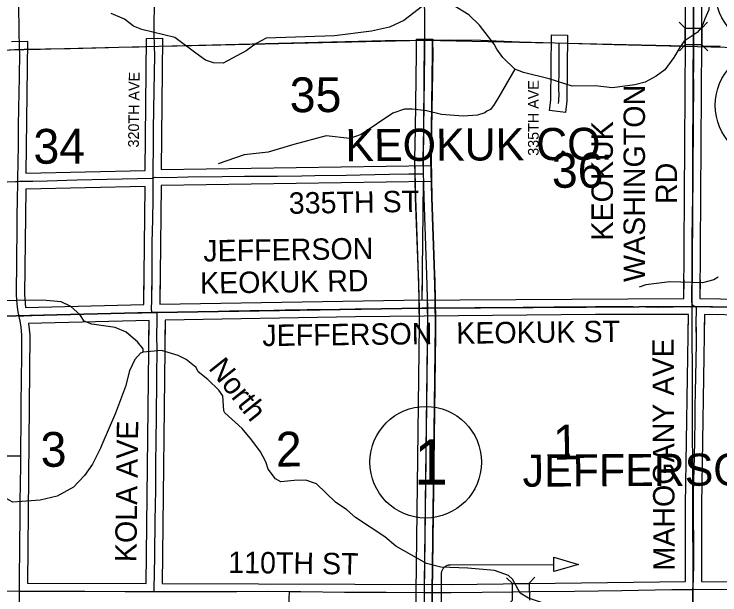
# Model space of a CAD drawing. Extents: x 10133 to 81668, y 7924 to 11018.
# Drawn here: x 11826.5 to 12222.4, y 8891.7 to 9217.2 of the extents above; entities that cross this region are included whole.
import ezdxf

# ---------------------------------------------------------------- set-up
doc = ezdxf.new("R2010")
doc.units = 0
for name, color, linetype in [('tdCoCityStreetMajor', 7, 'Continuous'), ('tdCoCityStreetMinor', 7, 'Continuous'), ('tdCoCorpPopTxt', 7, 'Continuous'), ('tdCoCorpTxt', 7, 'Continuous'), ('tdCoDirctArrow', 7, 'Continuous'), ('tdCoHydroRiver', 7, 'Continuous'), ('tdCoPriNonDiv', 7, 'Continuous'), ('tdCoRROwnerTxt', 7, 'Continuous'), ('tdCoSecRdTxt', 7, 'Continuous'), ('tdCoSectLinePart', 7, 'Continuous'), ('tdCoShieldCoRte', 7, 'Continuous'), ('tdCoShieldCoRteHrd', 7, 'Continuous'), ('tdCoShieldStRte', 7, 'Continuous'), ('tdCoStrucNonDivPri', 7, 'Continuous'), ('tdCoStrucSec', 7, 'Continuous'), ('tdCoSurfAsphalt', 7, 'Continuous'), ('tdCoSurfConc', 7, 'Continuous'), ('tdCoSurfGravel', 7, 'Continuous'), ('tdCoTwpBndryShd', 7, 'Continuous'), ('tdCoTwpNameTxt', 7, 'Continuous')]:
    doc.layers.add(name, color=color, linetype=linetype)

msp = doc.modelspace()

# ---------------------------------------------------------------- linework, layer by layer
at = {"layer": 'tdCoCityStreetMajor'}
for points in [[(11828.65, 9123.44), (11829.54, 9123.5), (11836.99, 9123.57), (11845.15, 9123.82), (11861.68, 9124.31), (11878.69, 9124.68), (11904.19, 9125.22), (11904.5, 9125.34), (11905.55, 9125.72), (11912.23, 9125.67), (11923.92, 9125.96), (11943.18, 9126.11), (11955.71, 9126.28), (11974.25, 9126.43), (11987.97, 9126.58)], [(11906.48, 8998.16), (11906.56, 9005.55), (11906.6, 9014.76), (11906.67, 9028.63), (11906.6, 9037.44), (11906.67, 9044.74), (11906.69, 9050.03)], [(11906.62, 9035.02), (11906.6, 9037.44), (11906.67, 9044.74), (11906.69, 9050.03)], [(12132.92, 9053.1), (12146.45, 9053.08), (12152.66, 9053.23), (12166.25, 9053.23), (12173.75, 9053.23), (12187.73, 9052.98), (12196.26, 9053.15), (12206.35, 9053.3), (12208.48, 9053.22)], [(12132.92, 9053.1), (12146.45, 9053.08), (12152.66, 9053.22), (12166.25, 9053.22), (12173.75, 9053.22), (12187.73, 9052.98), (12196.26, 9053.15), (12206.35, 9053.3), (12208.48, 9053.22)], [(11980.11, 8818.02), (11980.38, 8846.28), (11980.64, 8866.11), (11980.71, 8874.88), (11980.86, 8889.49), (11980.98, 8893.53)]]:
    msp.add_lwpolyline(points, dxfattribs=at)
at = {"layer": 'tdCoCityStreetMinor'}
for points in [[(12208.48, 9053.22), (12207.55, 9053.71), (12207.23, 9054.06), (12206.89, 9054.7), (12206.71, 9055.66), (12206.74, 9060.42), (12206.79, 9069.84), (12206.89, 9080.84), (12206.91, 9092.04), (12207.03, 9103.58), (12207.13, 9115.44), (12207.21, 9125.43), (12207.21, 9129.47), (12207.26, 9140.64), (12207.3, 9151.77), (12207.4, 9159.04), (12207.43, 9163.92), (12207.5, 9174.55), (12207.45, 9185.92), (12207.63, 9198), (12207.64, 9199.23), (12207.67, 9201.63), (12207.58, 9216.6), (12207.5, 9229.13)], [(12131.89, 9167.05), (12132.11, 9168.68), (12132.18, 9172.55), (12132.13, 9174.57), (12132.11, 9178.84), (12132.21, 9183.35), (12132.23, 9189.74), (12132.31, 9195.12), (12132.26, 9199.75), (12132.28, 9201.05)], [(11828.65, 9123.44), (11828.64, 9124.96), (11828.76, 9134.03), (11828.89, 9143.77), (11829.06, 9154.38), (11829.26, 9164.5), (11829.51, 9181.76), (11829.66, 9195.82), (11829.62, 9197.4)], [(11903.94, 9049.97), (11903.64, 9051.32), (11903.74, 9057.39), (11903.89, 9067.52), (11903.98, 9078.33), (11904.03, 9088.56), (11904.18, 9096.33), (11904.26, 9101.31), (11904.43, 9114.21), (11904.5, 9124.05), (11904.5, 9125.34), (11904.5, 9127.45), (11904.55, 9132.41), (11904.65, 9140.35), (11904.7, 9144.27), (11904.78, 9152.86), (11905.07, 9174.22), (11905.37, 9194.09), (11905.29, 9199.19)], [(11987.97, 9126.58), (11995.12, 9126.65), (12012.75, 9126.95), (12020.63, 9127.16), (12037.01, 9127.46), (12047.96, 9127.66), (12056, 9127.73)], [(11790.62, 9122.52), (11796.94, 9122.68), (11800.2, 9122.78), (11811.71, 9123.03), (11822.69, 9123.25), (11827.28, 9123.35), (11828.65, 9123.44)], [(11829.36, 9047.87), (11828.86, 9050.31), (11828.39, 9052.9), (11828.05, 9057.02), (11827.78, 9059.78), (11827.8, 9065.01), (11827.97, 9074.25), (11828.05, 9083.8), (11828.17, 9092.97), (11828.27, 9103.72), (11828.49, 9113.64), (11828.66, 9122.27), (11828.65, 9123.44)], [(12208.48, 9053.22), (12207.55, 9053.72), (12207.23, 9054.06), (12206.89, 9054.7), (12206.71, 9055.66), (12206.74, 9060.42), (12206.78, 9068.28)], [(11829.36, 9047.87), (11828.86, 9050.31), (11828.39, 9052.9), (11828.05, 9057.02), (11827.78, 9059.78), (11827.79, 9062.93)], [(11903.94, 9049.97), (11903.64, 9051.32), (11903.74, 9057.39), (11903.85, 9064.96)], [(11829.36, 9047.87), (11830.33, 9048.12), (11831.88, 9048.14), (11841.5, 9048.39), (11843.44, 9048.42), (11860.16, 9049.01), (11864.68, 9049.06), (11877.92, 9049.35), (11888.28, 9049.53), (11898.14, 9049.84), (11903.94, 9049.97)], [(11829.36, 9047.87), (11830.33, 9048.12), (11831.88, 9048.14), (11841.5, 9048.39), (11843.44, 9048.41), (11860.16, 9049.01), (11864.68, 9049.06), (11877.92, 9049.35), (11888.28, 9049.52), (11898.14, 9049.84), (11903.94, 9049.97)], [(11903.94, 9049.97), (11906.69, 9050.03), (11914.93, 9050.21), (11930.89, 9050.56), (11940.85, 9050.76), (11947.27, 9050.83), (11958.68, 9051.01), (11972.2, 9051.25), (11978.54, 9051.35), (11990.87, 9051.57), (12000.56, 9051.65), (12008.99, 9051.85), (12017.87, 9052), (12024.87, 9052.05), (12035.33, 9052.2), (12045.24, 9052.35), (12058.43, 9052.45), (12066.28, 9052.53), (12071.88, 9052.53), (12084.95, 9052.66), (12091.65, 9052.76), (12103.84, 9052.81), (12112.1, 9052.88), (12129.21, 9053.1), (12132.92, 9053.1)], [(11903.94, 9049.97), (11906.69, 9050.03), (11914.93, 9050.21), (11930.89, 9050.56), (11940.85, 9050.76), (11947.27, 9050.83), (11958.68, 9051), (11972.2, 9051.25), (11978.54, 9051.35), (11990.87, 9051.57), (12000.56, 9051.65), (12008.99, 9051.85), (12017.87, 9052), (12024.87, 9052.05), (12035.33, 9052.2), (12045.24, 9052.34), (12058.43, 9052.45), (12066.28, 9052.53), (12071.88, 9052.53), (12084.95, 9052.66), (12091.65, 9052.76), (12103.84, 9052.8), (12112.1, 9052.88), (12129.21, 9053.1), (12132.92, 9053.1)], [(12207.13, 8882.11), (12207.13, 8893.09), (12207.28, 8894.75), (12207.46, 8896.75), (12207.65, 8900.34), (12207.68, 8902.89), (12207.79, 8907.15), (12207.79, 8923.02), (12207.57, 8933.23), (12207.57, 8942.29), (12207.65, 8948.58), (12207.79, 8955.9), (12208.13, 8969.03), (12208.31, 8978.02), (12208.53, 8989.64), (12208.61, 8997.7), (12208.68, 9005.06), (12209.05, 9023.19), (12209.24, 9032.84), (12209.15, 9044.91), (12209.16, 9045.16), (12209.28, 9050.56), (12209.3, 9052.43), (12209.3, 9053.23)], [(12208.48, 9053.22), (12208.64, 9053.2), (12209.3, 9053.23)], [(12208.48, 9053.22), (12208.48, 9053.22)], [(12208.48, 9053.22), (12208.64, 9053.2), (12209.3, 9053.22)], [(12208.48, 9053.22), (12208.48, 9053.22)], [(12209.2, 9038.83), (12209.15, 9044.91), (12209.16, 9045.16), (12209.28, 9050.56), (12209.3, 9052.43), (12209.3, 9053.22)], [(12209.3, 9053.23), (12210.41, 9053.27), (12217.22, 9053.2), (12217.61, 9053.2), (12238.26, 9052.74), (12245.77, 9052.78), (12259.53, 9052.56), (12273.74, 9052.22), (12286.16, 9052.11), (12298.89, 9051.89), (12307.84, 9051.74), (12315.91, 9051.59), (12325.97, 9051.41), (12337.95, 9051.19), (12350.97, 9051), (12354.1, 9050.96)], [(12209.3, 9053.22), (12210.41, 9053.27), (12217.22, 9053.2), (12217.61, 9053.2), (12221.65, 9053.11)], [(11830.35, 8969.55), (11830.35, 8971.24), (11830.46, 8990.26), (11830.53, 8997.29), (11830.64, 9013.71), (11830.79, 9024.62), (11830.86, 9037.41), (11830.41, 9041.8), (11829.9, 9045.23), (11829.63, 9046.59), (11829.36, 9047.87)], [(11830.84, 9033.02), (11830.86, 9037.41), (11830.41, 9041.8), (11829.9, 9045.23), (11829.63, 9046.58), (11829.36, 9047.87)], [(11905.06, 8893.57), (11905.08, 8895.13), (11905.38, 8913.22), (11905.64, 8934.19), (11905.75, 8940.85), (11905.93, 8951.61), (11906.08, 8962.93), (11906.27, 8980.36), (11906.38, 8988.75), (11906.48, 8998.16)], [(11770.39, 8969.32), (11788, 8969.34), (11809.75, 8969.68), (11813.71, 8969.68), (11830.35, 8969.55)], [(11829.54, 8893.79), (11829.57, 8898.89), (11829.76, 8919.83), (11829.9, 8934.99), (11829.98, 8943.72), (11830.35, 8963.99), (11830.35, 8969.55)], [(11677.96, 8893.57), (11686.46, 8893.65), (11715.42, 8893.76), (11735.36, 8893.83), (11751.89, 8893.83), (11767.47, 8893.83), (11788.41, 8893.95), (11813.85, 8893.83), (11829.54, 8893.79)], [(11829.5, 8887.46), (11829.54, 8893.79)], [(11829.54, 8893.79), (11836.17, 8893.76), (11866.2, 8893.69), (11888.77, 8893.62), (11905.06, 8893.57)], [(11905.06, 8893.57), (11912.78, 8893.54), (11951.43, 8893.58), (11968.56, 8893.65), (11980.98, 8893.53), (11987.42, 8893.47), (12011.84, 8893.25), (12035.18, 8893.17), (12056.5, 8893.05)]]:
    msp.add_lwpolyline(points, dxfattribs=at)
at = {"layer": 'tdCoCorpPopTxt'}
msp.add_lwpolyline([(11905.29, 9199.19), (11905.17, 9206.37), (11905.22, 9227.48), (11905.09, 9246.02), (11905.02, 9248.69), (11905.01, 9248.71), (11904.97, 9250.08), (11904.98, 9251.46), (11905, 9254.8), (11905.02, 9257.72), (11905.02, 9258.16)], dxfattribs=at)
at = {"layer": 'tdCoDirctArrow'}
msp.add_lwpolyline([(12129.21, 8912.86), (12143.08, 8908.77), (12129.29, 8904.77)], close=True, dxfattribs=at)
msp.add_lwpolyline([(12066.36, 8840.71), (12066.29, 8903.61), (12066.33, 8904.15), (12066.38, 8904.48), (12066.47, 8904.91), (12066.61, 8905.33), (12066.78, 8905.73), (12066.99, 8906.12), (12067.23, 8906.48), (12067.5, 8906.83), (12067.8, 8907.14), (12068.13, 8907.44), (12068.48, 8907.7), (12068.86, 8907.92), (12069.25, 8908.12), (12069.66, 8908.28), (12070.08, 8908.4), (12070.51, 8908.48), (12070.94, 8908.53), (12071.38, 8908.54), (12129.25, 8908.69)], dxfattribs=at)
at = {"layer": 'tdCoHydroRiver'}
for points in [[(12218.49, 9227.41), (12217.11, 9223.38), (12216.42, 9222.18), (12216.23, 9219.57), (12213.95, 9214.56), (12213.05, 9211.94), (12212.14, 9209.79), (12209.59, 9206.9), (12202.34, 9202.03), (12200.03, 9198.91), (12196.59, 9192.93), (12191.51, 9185.97), (12186.6, 9182.33), (12180.5, 9179.14), (12174.61, 9177.61), (12162.09, 9175.96), (12152.36, 9176.97), (12139.58, 9176.73), (12126.72, 9181), (12112.21, 9184.52), (12107.44, 9186.33)], [(12055.65, 9221.61), (12045.14, 9213.61), (12037.16, 9209.91), (12027.02, 9207.59), (12006.23, 9205.08), (11967.89, 9203.67), (11962.26, 9200.73), (11956.65, 9196.6), (11943.75, 9189.74), (11938.31, 9189.87), (11933.78, 9191.45), (11928.5, 9195.38), (11916.73, 9204.16), (11898.19, 9208.56), (11893.42, 9210.37), (11888.37, 9214.3), (11880.97, 9217.48)], [(12107.44, 9186.33), (12100.69, 9192.84), (12097.29, 9197.51), (12095.82, 9200.32), (12087.57, 9211.07), (12081.55, 9216.88), (12072.45, 9222.39)], [(12107.44, 9186.33), (12098.49, 9170.77), (12095.72, 9166.46), (12093.64, 9163.82), (12091.76, 9162.84), (12090.6, 9161.87), (12086.36, 9160.61), (12078.32, 9159.99), (12066.23, 9160.95), (12057.9, 9162.93), (12049.83, 9163.97), (12045.57, 9163.89), (12038.98, 9161.64), (12021.2, 9149.71), (12014.85, 9147.46), (12001.57, 9148.88), (11983.42, 9144.05), (11969.05, 9139.76), (11955.58, 9138.33), (11940.99, 9133.33)], [(12221.44, 9069.72), (12218.99, 9068.31), (12212.63, 9066.53), (12194.38, 9067.15), (12180.91, 9065.48), (12177.15, 9064.23)], [(11893.46, 9035.42), (11889.44, 9038.85), (11883.23, 9041.58), (11870.17, 9043.47), (11865.88, 9045.05), (11863.45, 9048.8), (11858.37, 9053.35), (11852.86, 9056.01), (11842.4, 9056.88), (11812.5, 9056.44), (11791.37, 9056.49), (11781.18, 9055.46)], [(11898.87, 9027.66), (11898.84, 9029.55), (11895.69, 9033.52), (11889.43, 9038.85), (11883.23, 9041.58), (11870.17, 9043.47), (11865.88, 9045.05), (11863.44, 9048.8), (11858.37, 9053.35), (11855.4, 9054.78)], [(11898.87, 9027.66), (11897.46, 9027.16), (11894.21, 9023.55), (11891.25, 9017.33), (11889.04, 9008.53), (11883.39, 8993.51), (11875.66, 8975.85), (11874.99, 8973.94), (11870.42, 8964.86), (11866.03, 8958.62), (11859.76, 8952.11), (11850.62, 8946.97), (11841.19, 8944.67), (11825.81, 8943.68), (11823.66, 8944.82), (11818.87, 8947.58)], [(12057.78, 8909.32), (12040.56, 8918.95), (12034.54, 8924.28), (12018.01, 8935.11), (12013.19, 8939.29), (12006.72, 8943.67), (11996.12, 8953.89), (11990.16, 8955.92), (11983.53, 8955.79), (11976.21, 8954.95), (11973.09, 8956.79), (11968.97, 8962.16), (11967.71, 8966.16), (11964.77, 8971.79), (11959.91, 8978.33), (11954.35, 8984.86), (11944.72, 8993.68), (11944.22, 8994.86), (11943.6, 9003.14), (11941.41, 9006.41), (11935.14, 9012.45), (11929.85, 9016.62), (11928.62, 9019.2), (11923.1, 9023.6), (11918.56, 9025.88), (11909.27, 9028.56), (11898.87, 9027.66)], [(12228.37, 8852.05), (12220.43, 8858.77), (12216.37, 8861.06), (12204.46, 8864.4), (12187.38, 8866.45), (12178.07, 8870.31), (12165.23, 8873.63), (12159.27, 8875.89), (12145.87, 8883.45), (12137.79, 8884.97), (12125.21, 8886.39), (12114.97, 8889.76), (12110.42, 8892.52), (12106.01, 8900.49), (12103.84, 8902.58), (12095.98, 8905.28), (12081.04, 8906.66), (12065.87, 8907.1), (12057.78, 8909.32)]]:
    msp.add_lwpolyline(points, dxfattribs=at)
at = {"layer": 'tdCoPriNonDiv'}
for points in [[(12222.27, 9351.02), (12211.8, 9351.25), (12212.17, 9201.66), (12211.22, 9057.76), (12221.68, 9057.59)], [(11825.03, 9201.8), (11834.02, 9202), (11833.18, 9128.03), (11900.03, 9129.63), (11900.72, 9203.61), (11909.71, 9203.76), (11909.03, 9130.19), (12060.45, 9132.27), (12060.54, 9123.28), (11908.98, 9121.19), (11908.19, 9054.56), (12045.21, 9056.84), (12202.23, 9057.74), (12203.18, 9201.65), (12202.93, 9275.8)], [(12135.74, 9161.99), (12126.82, 9163.2), (12127.62, 9169.03), (12127.87, 9205.64), (12136.87, 9205.46), (12136.61, 9168.59), (12135.74, 9161.99)], [(11833, 9052.67), (11899.19, 9054.37), (11899.98, 9120.63), (11833.1, 9119.03), (11832.28, 9059.99), (11833, 9052.67)], [(11908.31, 9065.06), (11908.19, 9054.56), (12045.21, 9056.84), (12202.23, 9057.74), (12202.29, 9068.26)], [(12211.29, 9068.21), (12211.22, 9057.76), (12349.74, 9055.52), (12349.79, 9066.03)], [(11832.32, 9063.05), (11832.28, 9059.99), (11833, 9052.67)], [(11833, 9052.67), (11899.19, 9054.37), (11899.31, 9064.84)], [(12071.67, 8897.56), (12203.08, 8899.2), (12203.07, 8942.34), (12204.74, 9048.78), (12152.72, 9048.73), (12017.92, 9047.5), (11911.17, 9045.63), (11909.63, 8898.05), (12071.67, 8897.56)], [(12204.57, 9038.28), (12204.74, 9048.78), (12152.72, 9048.73), (12017.92, 9047.5), (11911.17, 9045.63), (11911.06, 9035.09)], [(12349.95, 8898.47), (12349.53, 9046.52), (12213.74, 9048.74), (12212.07, 8942.26), (12212.09, 8899.24), (12254.04, 8898.89), (12349.95, 8898.47)], [(12220.9, 9048.62), (12213.74, 9048.74), (12213.6, 9040.05)], [(11902.17, 9028.62), (11902.18, 9045.43), (11834.68, 9043.72), (11835.36, 9037.39), (11834.07, 8898.27), (11900.63, 8898.08), (11902.17, 9028.62)], [(11902.17, 9034.92), (11902.18, 9045.43), (11834.68, 9043.72), (11835.36, 9037.39), (11835.32, 9033.14)]]:
    msp.add_lwpolyline(points, dxfattribs=at)
at = {"layer": 'tdCoSectLinePart'}
msp.add_lwpolyline([(12056.5, 8893.05), (12071.69, 8893.06), (12106.46, 8893.32), (12116.41, 8893.47), (12140.86, 8893.73), (12167.39, 8894.17), (12195.46, 8894.62), (12207.28, 8894.75), (12208.74, 8894.76), (12230.16, 8894.65), (12254.02, 8894.39), (12271.85, 8894.39), (12294.08, 8894.17), (12316.8, 8894.05), (12322.49, 8894.02), (12344.54, 8893.95), (12354.49, 8894), (12360.07, 8894.02), (12388.33, 8894.21), (12408.9, 8894.39)], dxfattribs=at)
at = {"layer": 'tdCoShieldCoRte'}
for points in [[(12199.59, 9212.61), (12202.92, 9209.3), (12212.3, 9209.34)], [(12215.54, 9212.6), (12212.3, 9209.34), (12212.34, 9199.95)], [(12199.65, 9196.59), (12202.95, 9199.92), (12202.92, 9209.3)], [(12215.67, 9196.65), (12212.34, 9199.95), (12202.95, 9199.92)], [(12102.65, 8901.27), (12106.02, 8898.01), (12115.4, 8898.15)], [(12118.67, 8901.51), (12115.4, 8898.15), (12115.54, 8888.76)], [(12102.89, 8885.26), (12106.16, 8888.62), (12106.02, 8898.01)]]:
    msp.add_lwpolyline(points, dxfattribs=at)
at = {"layer": 'tdCoShieldCoRteHrd'}
for points in [[(12207.52, 9180.78), (12206.7, 9053.29)], [(12334.13, 9051.28), (12206.71, 9053.29)]]:
    msp.add_lwpolyline(points, dxfattribs=at)
at = {"layer": 'tdCoStrucNonDivPri'}
for points in [[(12056.38, 9273.51), (12056.79, 9202.66)], [(11909.79, 9199.29), (12056.79, 9202.66)], [(12056.16, 9132.2), (12056.79, 9202.66)], [(12056.79, 9202.66), (12127.84, 9201.04)], [(12136.84, 9200.84), (12203.15, 9199.33)], [(12212.15, 9199.3), (12222.64, 9199.48)], [(12055.48, 9056.94), (12056.08, 9123.2)], [(12055.48, 9056.94), (12055.57, 9067.42)], [(12058.38, 9047.87), (12056.55, 8897.61)], [(12058.38, 9047.87), (12058.25, 9037.45)]]:
    msp.add_lwpolyline(points, dxfattribs=at)
at = {"layer": 'tdCoStrucSec'}
for points in [[(11448.12, 9188.29), (11485.13, 9189.73), (11511.4, 9190.16), (11538.73, 9191.44), (11548.63, 9191.5), (11569.79, 9192.29), (11593.85, 9192.84), (11616.2, 9193.63), (11652.37, 9194.07), (11752.87, 9195.82), (11770.92, 9195.82), (11885.25, 9198.58), (12034.74, 9202.48), (12056.79, 9202.66), (12070.8, 9202.78), (12088.36, 9202.53), (12109.96, 9201.59), (12163.18, 9200.16), (12264.21, 9197.78)], [(12056.79, 9202.66), (12056.71, 9201.83), (12056.79, 9195.48), (12056.2, 9152.67), (12055.85, 9135.99), (12056.25, 9114.34), (12057.87, 9071.04), (12058.44, 9052.45), (12058.39, 9037.45)], [(12057.98, 9067.44), (12058.46, 9043.29), (12056.5, 8893.05), (12056.26, 8818.14), (12055.8, 8774.51), (12053.58, 8699.71), (12053, 8667.35), (12053.63, 8622.55), (12053.62, 8591.78), (12053.06, 8516.92), (12052.96, 8510.55)]]:
    msp.add_lwpolyline(points, dxfattribs=at)
at = {"layer": 'tdCoSurfAsphalt'}
for p, q in [((12052.31, 9203.09), (12061.42, 9203.09)), ((12052.33, 9203.1), (12061.45, 9203.1)), ((12061.42, 9203.09), (12061.27, 9202.24)), ((12061.45, 9203.1), (12061.29, 9202.25))]:
    msp.add_line(p, q, dxfattribs=at)
for points in [[(12053.89, 9037.47), (12053.94, 9052.39), (12053.38, 9070.89), (12051.75, 9114.22), (12051.35, 9136), (12051.7, 9152.74), (12052.29, 9195.48), (12052.21, 9202.02), (12052.31, 9203.09)], [(12053.91, 9038.1), (12053.96, 9052.4), (12053.4, 9070.9), (12051.77, 9114.23), (12051.38, 9136.01), (12051.72, 9152.75), (12052.31, 9195.49), (12052.23, 9202.03), (12052.33, 9203.1)], [(12051.78, 8818.18), (12052.02, 8893.1), (12053.98, 9043.29), (12053.94, 9045.48), (12053.96, 9052.4), (12053.4, 9070.9), (12051.77, 9114.23), (12051.38, 9136.01), (12051.72, 9152.75), (12052.31, 9195.49), (12052.23, 9202.03), (12052.33, 9203.1), (12061.45, 9203.1), (12061.29, 9202.25), (12061.24, 9201.66), (12061.31, 9195.48), (12060.72, 9152.6), (12060.38, 9136), (12060.77, 9114.48), (12062.4, 9071.2), (12062.49, 9068.02), (12062.94, 9045.56), (12062.91, 9038.03), (12061.02, 8893.03), (12060.78, 8818.12)], [(12062.89, 9037.44), (12062.94, 9052.51), (12062.37, 9071.19), (12060.75, 9114.47), (12060.35, 9135.99), (12060.7, 9152.59), (12061.29, 9195.47), (12061.21, 9201.65), (12061.27, 9202.24)], [(12062.91, 9038.03), (12062.96, 9052.52), (12062.4, 9071.2), (12060.77, 9114.48), (12060.38, 9136), (12060.72, 9152.6), (12061.31, 9195.48), (12061.24, 9201.66), (12061.29, 9202.25)], [(12050.27, 8739.76), (12051.3, 8774.6), (12051.76, 8818.17), (12052, 8893.09), (12053.96, 9043.28), (12053.48, 9067.35)], [(12050.29, 8739.77), (12051.32, 8774.61), (12051.78, 8818.18), (12052.02, 8893.1), (12053.98, 9043.29), (12053.47, 9069.08)], [(12058.99, 8730.14), (12060.3, 8774.41), (12060.76, 8818.11), (12061, 8893.02), (12062.96, 9043.31), (12062.48, 9067.53)], [(12059.01, 8730.15), (12060.32, 8774.43), (12060.78, 8818.12), (12061.02, 8893.03), (12062.98, 9043.32), (12062.47, 9069.34)]]:
    msp.add_lwpolyline(points, dxfattribs=at)
at = {"layer": 'tdCoSurfConc'}
for centre in [(12251.05, 9230), (12251.05, 9166.15), (12057.38, 8966.01)]:
    msp.add_circle(centre, 31.27, dxfattribs=at)
at = {"layer": 'tdCoSurfGravel'}
msp.add_lwpolyline([(11753.46, 9257.83), (11752.84, 9195.79), (11756.05, 9195.78), (11760.21, 9195.72), (11770.92, 9195.82), (11779.7, 9196.02), (11791.46, 9196.37), (11799.57, 9196.61), (11823.82, 9197.18), (11826.76, 9197.29), (11829.62, 9197.4), (11832.17, 9197.5), (11841.4, 9197.6), (11844.16, 9197.65), (11857.97, 9197.94), (11879.42, 9198.53), (11885.24, 9198.58), (11896.44, 9198.93), (11905.29, 9199.19), (11905.17, 9206.37), (11905.22, 9227.48)], dxfattribs=at)
at = {"layer": 'tdCoTwpBndryShd'}
msp.add_lwpolyline([(11829.62, 9197.4), (11829.36, 9208.99), (11829.26, 9220.92), (11829.16, 9227.52), (11829.22, 9233.28), (11829.23, 9234.84), (11829.31, 9236.42), (11829.43, 9237.9), (11829.95, 9239.16), (11831.43, 9242.09), (11831.62, 9242.87), (11831.82, 9243.65), (11832.07, 9245.18), (11832.14, 9247.54), (11832.02, 9252.16), (11832.01, 9252.93), (11831.94, 9261.21), (11831.92, 9262.89)], dxfattribs=at)
at = {"layer": 'tdCoTwpNameTxt'}
for points in [[(12204.65, 9594.91), (12205.81, 9506.76), (12207.26, 9355.85), (12207.65, 9199.23), (12206.71, 9053.29), (12058.44, 9052.45), (12055.44, 9052.43), (11906.7, 9050.03), (11903.62, 9049.96), (11751.72, 9046.27), (11602.3, 9041.92), (11599.58, 9041.89), (11448.66, 9038.75), (11287.47, 9032.68), (11137.48, 9029.42), (10987.91, 9025.85), (10954.88, 9025.06)], [(10954.88, 9025.06), (10987.91, 9025.85), (11137.48, 9029.42), (11287.46, 9032.68), (11448.65, 9038.75), (11599.58, 9041.89), (11602.29, 9041.92), (11751.71, 9046.27), (11903.62, 9049.96), (11906.69, 9050.03), (12055.44, 9052.43), (12058.43, 9052.45), (12206.7, 9053.29), (12354.1, 9050.96), (12408.9, 9050.4)], [(12206.7, 9053.29), (12207.28, 8894.75), (12205.62, 8743.86), (12204.79, 8593.78), (12204.03, 8510.55)]]:
    msp.add_lwpolyline(points, dxfattribs=at)

# ---------------------------------------------------------------- texts
at = {"layer": 'tdCoCorpTxt'}
msp.add_text('North', height=12, rotation=308.5136, dxfattribs=at).set_placement((11935.16, 9018.56))
at = {"layer": 'tdCoRROwnerTxt'}
for s, rotation, p in [('35', 0.2308, (11981.13, 9162.19)), ('34', 0.2301, (11837.39, 9133.31)), ('36', 0.2315, (12128.18, 9119.84)), ('1', 1.1469, (12129.07, 8967.39)), ('3', 1.1455, (11841.57, 8963.31)), ('2', 1.1462, (11973.52, 8963.45))]:
    msp.add_text(s, height=19.5, rotation=rotation, dxfattribs=at).set_placement(p)
at = {"layer": 'tdCoSecRdTxt'}
for s, p in [('KEOKUK CO.', (12012.39, 9134.72)), ('JEFFERSON CO.', (12111.79, 8952.27))]:
    msp.add_text(s, height=18, rotation=0.3231, dxfattribs=at).set_placement(p)
at = {"layer": 'tdCoShieldStRte'}
for s, height, rotation, p in [('320TH AVE', 6, 89.3868, (11896.45, 9142.41)), ('335TH AVE', 6, 90, (12120.76, 9137.79)), ('WASHINGTON', 12, 90, (12180.37, 9067.03)), ('KEOKUK', 12, 90, (12162.37, 9090.25)), ('RD', 12, 90, (12198.37, 9110.74)), ('335TH ST', 12, 0.866, (11980.66, 9105.23)), ('JEFFERSON', 12, 0.866, (11932.72, 9078.47)), ('KEOKUK RD', 12, 0.866, (11930.88, 9060.44)), ('JEFFERSON   KEOKUK ST', 12, 0.6768, (11965.82, 9031.08)), ('MAHOGANY AVE', 12, 90.2617, (12197.11, 8905.28)), ('KOLA AVE', 12, 89.2158, (11895.09, 8909.93)), ('110TH ST', 12, 359.2458, (11946.54, 8903.97))]:
    msp.add_text(s, height=height, rotation=rotation, dxfattribs=at).set_placement(p)
at = {"layer": 'tdCoSurfConc'}
msp.add_text('1', height=25.5, dxfattribs=at).set_placement((12050.91, 8953.43))

doc.saveas('drawing.dxf')
